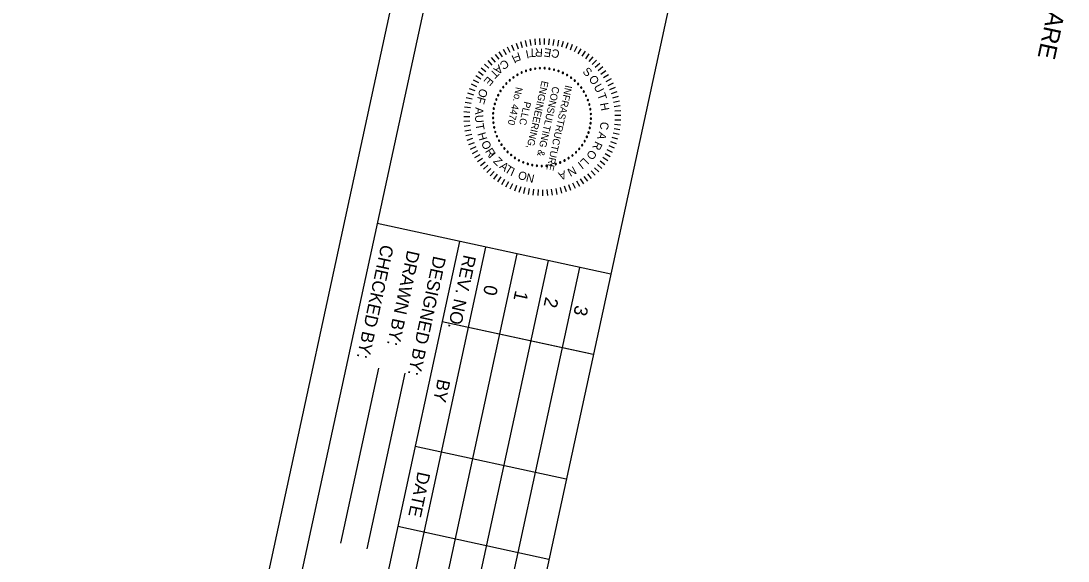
# Model space of a CAD drawing. Extents: x 1897817 to 2050613, y 442539 to 798440.
# Drawn here: x 1976813 to 1977576, y 783329 to 783723 of the extents above; entities that cross this region are included whole.
import ezdxf

# ---------------------------------------------------------------- set-up
doc = ezdxf.new("R2010")
doc.units = 0
for name, color, linetype in [('Default', 7, 'Continuous'), ('RD_SHT_Bndy', 7, 'Continuous'), ('RD_SHT_IplotShp', 7, 'Continuous')]:
    doc.layers.add(name, color=color, linetype=linetype)

msp = doc.modelspace()

# ---------------------------------------------------------------- linework, layer by layer
at = {"layer": 'Default'}
for p, q in [((1977174.02, 783706.47), (1977175.5, 783702.32)), ((1977177.35, 783707.54), (1977178.57, 783703.3)), ((1977180.73, 783708.4), (1977181.69, 783704.1)), ((1977184.16, 783709.06), (1977184.86, 783704.71)), ((1977187.62, 783709.5), (1977188.06, 783705.12)), ((1977191.11, 783709.74), (1977191.28, 783705.33)), ((1977194.6, 783709.76), (1977194.5, 783705.35)), ((1977198.09, 783709.57), (1977197.72, 783705.18)), ((1977201.56, 783709.16), (1977200.92, 783704.8)), ((1977205, 783708.55), (1977204.1, 783704.24)), ((1977208.39, 783707.72), (1977207.23, 783703.48)), ((1977211.73, 783706.7), (1977210.31, 783702.53)), ((1977158.7, 783698.21), (1977161.36, 783694.7)), ((1977161.55, 783700.23), (1977163.99, 783696.56)), ((1977164.52, 783702.07), (1977166.73, 783698.26)), ((1977167.6, 783703.73), (1977169.57, 783699.79)), ((1977170.77, 783705.2), (1977172.5, 783701.15)), ((1977215, 783705.47), (1977213.33, 783701.39)), ((1977218.19, 783704.04), (1977216.27, 783700.07)), ((1977221.28, 783702.42), (1977219.13, 783698.58)), ((1977224.27, 783700.62), (1977221.89, 783696.91)), ((1977227.15, 783698.63), (1977224.54, 783695.08)), ((1977150.96, 783691.17), (1977154.21, 783688.2)), ((1977153.4, 783693.68), (1977156.46, 783690.51)), ((1977155.98, 783696.03), (1977158.85, 783692.68)), ((1977229.9, 783696.48), (1977227.08, 783693.09)), ((1977232.51, 783694.16), (1977229.49, 783690.95)), ((1977234.98, 783691.68), (1977231.77, 783688.67)), ((1977146.57, 783685.74), (1977150.16, 783683.19)), ((1977148.68, 783688.52), (1977152.11, 783685.76)), ((1977237.29, 783689.07), (1977233.9, 783686.25)), ((1977239.43, 783686.31), (1977235.88, 783683.71)), ((1977241.41, 783683.43), (1977237.7, 783681.05)), ((1977141.3, 783676.7), (1977145.29, 783674.84)), ((1977142.87, 783679.82), (1977146.75, 783677.72)), ((1977144.63, 783682.84), (1977148.37, 783680.51)), ((1977243.2, 783680.43), (1977239.36, 783678.28)), ((1977244.81, 783677.33), (1977240.85, 783675.42)), ((1977138.74, 783670.2), (1977142.93, 783668.85)), ((1977139.92, 783673.49), (1977144.02, 783671.88)), ((1977246.23, 783674.14), (1977242.15, 783672.47)), ((1977247.45, 783670.87), (1977243.28, 783669.45)), ((1977136.99, 783663.44), (1977141.32, 783662.61)), ((1977137.76, 783666.85), (1977142.03, 783665.75)), ((1977248.47, 783667.53), (1977244.22, 783666.37)), ((1977249.28, 783664.13), (1977244.97, 783663.23)), ((1977249.89, 783660.69), (1977245.53, 783660.05)), ((1977135.94, 783653.03), (1977140.35, 783653)), ((1977136.08, 783656.52), (1977140.47, 783656.22)), ((1977136.43, 783660), (1977140.8, 783659.43)), ((1977250.28, 783657.22), (1977245.89, 783656.85)), ((1977250.46, 783653.73), (1977246.06, 783653.63)), ((1977136.01, 783649.54), (1977140.41, 783649.77)), ((1977136.3, 783646.06), (1977140.68, 783646.56)), ((1977250.18, 783646.75), (1977245.8, 783647.19)), ((1977250.43, 783650.24), (1977246.03, 783650.41)), ((1977136.8, 783642.6), (1977141.14, 783643.37)), ((1977137.51, 783639.18), (1977141.79, 783640.21)), ((1977248.18, 783636.48), (1977243.95, 783637.71)), ((1977249.06, 783639.86), (1977244.76, 783640.83)), ((1977249.73, 783643.29), (1977245.38, 783643.99)), ((1977138.43, 783635.81), (1977142.64, 783637.1)), ((1977139.55, 783632.5), (1977143.67, 783634.05)), ((1977140.87, 783629.27), (1977144.89, 783631.06)), ((1977245.83, 783629.91), (1977241.78, 783631.64)), ((1977247.11, 783633.16), (1977242.96, 783634.64)), ((1977142.38, 783626.12), (1977146.29, 783628.15)), ((1977144.08, 783623.07), (1977147.86, 783625.34)), ((1977145.97, 783620.13), (1977149.6, 783622.63)), ((1977240.83, 783620.71), (1977237.17, 783623.15)), ((1977242.68, 783623.67), (1977238.88, 783625.89)), ((1977244.35, 783626.74), (1977240.41, 783628.72)), ((1977148.03, 783617.31), (1977151.5, 783620.02)), ((1977150.26, 783614.62), (1977153.56, 783617.54)), ((1977152.65, 783612.07), (1977155.77, 783615.19)), ((1977234.25, 783612.57), (1977231.09, 783615.64)), ((1977236.61, 783615.15), (1977233.27, 783618.02)), ((1977238.81, 783617.87), (1977235.3, 783620.53)), ((1977155.19, 783609.68), (1977158.11, 783612.98)), ((1977157.87, 783607.44), (1977160.59, 783610.91)), ((1977160.69, 783605.37), (1977163.18, 783609)), ((1977163.62, 783603.47), (1977165.89, 783607.25)), ((1977223.39, 783603.84), (1977221.06, 783607.58)), ((1977226.3, 783605.77), (1977223.75, 783609.36)), ((1977229.09, 783607.87), (1977226.32, 783611.3)), ((1977231.74, 783610.14), (1977228.77, 783613.4)), ((1977166.66, 783601.76), (1977168.7, 783605.67)), ((1977169.81, 783600.24), (1977171.6, 783604.26)), ((1977173.04, 783598.91), (1977174.58, 783603.03)), ((1977176.34, 783597.78), (1977177.63, 783601.99)), ((1977179.71, 783596.85), (1977180.74, 783601.14)), ((1977183.13, 783596.13), (1977183.9, 783600.47)), ((1977186.58, 783595.62), (1977187.09, 783600)), ((1977190.06, 783595.33), (1977190.3, 783599.72)), ((1977193.56, 783595.24), (1977193.52, 783599.65)), ((1977197.05, 783595.37), (1977196.75, 783599.76)), ((1977200.52, 783595.71), (1977199.95, 783600.08)), ((1977203.97, 783596.26), (1977203.14, 783600.59)), ((1977207.38, 783597.02), (1977206.28, 783601.29)), ((1977210.74, 783597.99), (1977209.38, 783602.18)), ((1977214.03, 783599.16), (1977212.42, 783603.26)), ((1977217.24, 783600.53), (1977215.39, 783604.52)), ((1977220.37, 783602.09), (1977218.27, 783605.97)), ((1977243, 783538.14), (1977072.76, 783574.99)), ((1977132.8, 783561.98), (1977007.28, 782982.14)), ((1977151.76, 783557.88), (1977026.24, 782978.03)), ((1977174.51, 783552.96), (1977049.07, 782973.09)), ((1977197.34, 783548.01), (1977071.82, 782968.16)), ((1977220.24, 783543.06), (1977094.67, 782963.3)), ((1977120.09, 783503.65), (1977230.29, 783479.8)), ((1977120.09, 783503.65), (1977226.93, 783480.53)), ((1977073.83, 783469.6), (1977046.15, 783342.08)), ((1977092.95, 783465.86), (1977065.2, 783338.04)), ((1977100.52, 783412.86), (1977210.62, 783388.95)), ((1977087.87, 783354.44), (1977197.98, 783330.52))]:
    msp.add_line(p, q, dxfattribs=at)
for centre, start, end in [((1977175.02, 783683.42), 30.23602, 210.23602), ((1977175.02, 783683.42), 210.23602, 30.23602), ((1977178.08, 783685.01), 24.69756, 204.69756), ((1977178.08, 783685.01), 204.69756, 24.69756), ((1977181.28, 783686.29), 19.15909, 199.15909), ((1977181.28, 783686.29), 199.15909, 19.15909), ((1977184.59, 783687.25), 13.62063, 193.62063), ((1977184.59, 783687.25), 193.62063, 13.62063), ((1977187.98, 783687.9), 8.08217, 188.08217), ((1977187.98, 783687.9), 188.08217, 8.08217), ((1977191.41, 783688.21), 2.54371, 182.54371), ((1977191.41, 783688.21), 182.54371, 2.54371), ((1977194.86, 783688.19), 357.00525, 177.00525), ((1977194.86, 783688.19), 177.00525, 357.00525), ((1977198.29, 783687.83), 171.46679, 351.46679), ((1977198.29, 783687.83), 351.46679, 171.46679), ((1977201.67, 783687.15), 165.92833, 345.92833), ((1977201.67, 783687.15), 345.92833, 165.92833), ((1977204.96, 783686.15), 160.38986, 340.38986), ((1977204.96, 783686.15), 340.38986, 160.38986), ((1977208.15, 783684.83), 154.8514, 334.8514), ((1977208.15, 783684.83), 334.8514, 154.8514), ((1977211.19, 783683.21), 149.31294, 329.31294), ((1977211.19, 783683.21), 329.31294, 149.31294), ((1977166.94, 783677.01), 46.8514, 226.8514), ((1977166.94, 783677.01), 226.8514, 46.8514), ((1977169.42, 783679.41), 41.31294, 221.31294), ((1977169.42, 783679.41), 221.31294, 41.31294), ((1977172.12, 783681.55), 35.77448, 215.77448), ((1977172.12, 783681.55), 215.77448, 35.77448), ((1977214.07, 783681.3), 143.77448, 323.77448), ((1977214.07, 783681.3), 323.77448, 143.77448), ((1977216.74, 783679.13), 138.23602, 318.23602), ((1977216.74, 783679.13), 318.23602, 138.23602), ((1977219.19, 783676.7), 132.69756, 312.69756), ((1977219.19, 783676.7), 312.69756, 132.69756), ((1977161.03, 783668.56), 63.46679, 243.46679), ((1977161.03, 783668.56), 243.46679, 63.46679), ((1977162.72, 783671.57), 57.92833, 237.92833), ((1977162.72, 783671.57), 237.92833, 57.92833), ((1977164.7, 783674.39), 52.38986, 232.38986), ((1977164.7, 783674.39), 232.38986, 52.38986), ((1977221.4, 783674.06), 127.15909, 307.15909), ((1977221.4, 783674.06), 307.15909, 127.15909), ((1977223.34, 783671.21), 121.62063, 301.62063), ((1977223.34, 783671.21), 301.62063, 121.62063), ((1977225, 783668.18), 116.08217, 296.08217), ((1977225, 783668.18), 296.08217, 116.08217), ((1977158.55, 783662.14), 74.54371, 254.54371), ((1977158.55, 783662.14), 254.54371, 74.54371), ((1977159.64, 783665.41), 69.00525, 249.00525), ((1977159.64, 783665.41), 249.00525, 69.00525), ((1977226.36, 783665.01), 110.54371, 290.54371), ((1977226.36, 783665.01), 290.54371, 110.54371), ((1977227.4, 783661.73), 105.00525, 285.00525), ((1977227.4, 783661.73), 285.00525, 105.00525), ((1977157.25, 783651.91), 91.15909, 271.15909), ((1977157.35, 783655.35), 85.62063, 265.62063), ((1977157.25, 783651.91), 271.15909, 91.15909), ((1977157.79, 783658.77), 80.08217, 260.08217), ((1977157.35, 783655.35), 265.62063, 85.62063), ((1977157.79, 783658.77), 260.08217, 80.08217), ((1977228.13, 783658.36), 99.46679, 279.46679), ((1977228.52, 783654.93), 93.92833, 273.92833), ((1977228.13, 783658.36), 279.46679, 99.46679), ((1977228.52, 783654.93), 273.92833, 93.92833), ((1977157.48, 783648.47), 96.69756, 276.69756), ((1977157.48, 783648.47), 276.69756, 96.69756), ((1977158.04, 783645.07), 102.23602, 282.23602), ((1977158.04, 783645.07), 282.23602, 102.23602), ((1977227.72, 783644.65), 77.31294, 257.31294), ((1977227.72, 783644.65), 257.31294, 77.31294), ((1977228.32, 783648.05), 82.8514, 262.8514), ((1977228.59, 783651.49), 88.38986, 268.38986), ((1977228.32, 783648.05), 262.8514, 82.8514), ((1977228.59, 783651.49), 268.38986, 88.38986), ((1977158.92, 783641.73), 107.77448, 287.77448), ((1977158.92, 783641.73), 287.77448, 107.77448), ((1977160.13, 783638.5), 113.31294, 293.31294), ((1977160.13, 783638.5), 293.31294, 113.31294), ((1977225.55, 783638.12), 66.23602, 246.23602), ((1977225.55, 783638.12), 246.23602, 66.23602), ((1977226.79, 783641.33), 71.77448, 251.77448), ((1977226.79, 783641.33), 251.77448, 71.77448), ((1977161.64, 783635.4), 118.8514, 298.8514), ((1977161.64, 783635.4), 298.8514, 118.8514), ((1977163.44, 783632.46), 124.38986, 304.38986), ((1977163.44, 783632.46), 304.38986, 124.38986), ((1977165.52, 783629.71), 129.92833, 309.92833), ((1977165.52, 783629.71), 309.92833, 129.92833), ((1977220.06, 783629.39), 49.62063, 229.62063), ((1977220.06, 783629.39), 229.62063, 49.62063), ((1977222.17, 783632.12), 55.15909, 235.15909), ((1977222.17, 783632.12), 235.15909, 55.15909), ((1977224, 783635.03), 60.69756, 240.69756), ((1977224, 783635.03), 240.69756, 60.69756), ((1977167.85, 783627.17), 135.46679, 315.46679), ((1977167.85, 783627.17), 315.46679, 135.46679), ((1977170.42, 783624.87), 141.00525, 321.00525), ((1977170.42, 783624.87), 321.00525, 141.00525), ((1977173.19, 783622.83), 146.54371, 326.54371), ((1977173.19, 783622.83), 326.54371, 146.54371), ((1977212.3, 783622.6), 33.00525, 213.00525), ((1977212.3, 783622.6), 213.00525, 33.00525), ((1977215.1, 783624.61), 38.54371, 218.54371), ((1977215.1, 783624.61), 218.54371, 38.54371), ((1977217.69, 783626.88), 44.08217, 224.08217), ((1977217.69, 783626.88), 224.08217, 44.08217), ((1977176.15, 783621.06), 152.08217, 332.08217), ((1977176.15, 783621.06), 332.08217, 152.08217), ((1977179.27, 783619.59), 157.62063, 337.62063), ((1977179.27, 783619.59), 337.62063, 157.62063), ((1977182.52, 783618.43), 163.15909, 343.15909), ((1977182.52, 783618.43), 343.15909, 163.15909), ((1977185.86, 783617.58), 348.69756, 168.69756), ((1977185.86, 783617.58), 168.69756, 348.69756), ((1977189.27, 783617.07), 174.23602, 354.23602), ((1977189.27, 783617.07), 354.23602, 174.23602), ((1977192.71, 783616.88), 359.77448, 179.77448), ((1977192.71, 783616.88), 179.77448, 359.77448), ((1977196.16, 783617.03), 5.31294, 185.31294), ((1977196.16, 783617.03), 185.31294, 5.31294), ((1977199.57, 783617.5), 10.8514, 190.8514), ((1977199.57, 783617.5), 190.8514, 10.8514), ((1977202.92, 783618.31), 16.38986, 196.38986), ((1977202.92, 783618.31), 196.38986, 16.38986), ((1977206.18, 783619.43), 21.92833, 201.92833), ((1977206.18, 783619.43), 201.92833, 21.92833), ((1977209.32, 783620.87), 27.46679, 207.46679), ((1977209.32, 783620.87), 207.46679, 27.46679)]:
    msp.add_arc(centre, 0.485, start, end, dxfattribs=at)
at = {"layer": 'RD_SHT_Bndy'}
for p, q in [((1977385.46, 785019.62), (1976842.49, 782511.26)), ((1977388.81, 784211.78), (1977012.76, 782474.48)), ((1977243, 783538.13), (1977072.76, 783575.06))]:
    msp.add_line(p, q, dxfattribs=at)
at = {"layer": 'RD_SHT_IplotShp'}
msp.add_lwpolyline([(1977366.14, 785041.72), (1976813.35, 782487.96), (1978459.81, 782131.57), (1979012.6, 784685.33)], close=True, dxfattribs=at)

# ---------------------------------------------------------------- texts
at = {"layer": 'Default'}
for s, height, rotation, p in [('ITS DEVICES/SYMBOLOGY (CAMERA, SERVICE BOX, DMS, CABINET, ETC.) ARE SCALED UP FOR VISIBILITY ON PLANS, THEY ARE', 12.70566, 257.78611, (1977779.42, 784738.12)), ('F', 6.03, 197.55738, (1977176.3, 783699.98)), ('I', 6.03, 191.55738, (1977182.72, 783701.5)), ('T', 6.03, 182.81115, (1977188.1, 783702.44)), ('R', 6.03, 176.81115, (1977193.68, 783702.46)), ('E', 6.03, 170.81115, (1977200.11, 783701.98)), ('C', 6.03, 164.81115, (1977206.36, 783700.93)), ('A', 6.03, 218.31294, (1977161.45, 783691.11)), ('C', 6.03, 212.31294, (1977166.43, 783694.93)), ('I', 6.03, 206.31294, (1977172.04, 783697.92)), ('T', 6.03, 224.31294, (1977158.05, 783687.99)), ('S', 6.03, 316.69438, (1977222.06, 783685.15)), ('E', 6.03, 230.31294, (1977153.53, 783682.7)), ('ENGINEERING,', 5.1733, 257.31294, (1977192.72, 783679.31)), ('INFRASTRUCTURE', 5.1733, 257.31294, (1977210.01, 783676.11)), ('O', 6.03, 307.66435, (1977226.53, 783680.26)), ('U', 6.03, 298.63433, (1977230.35, 783674.69)), ('O', 6.03, 248.31294, (1977148.17, 783673.94)), ('No. 4470', 5.173, 257.31294, (1977173.99, 783674.72)), ('CONSULTING &', 5.1733, 257.31294, (1977200.71, 783675.21)), ('T', 6.03, 289.6043, (1977233.07, 783668.91)), ('F', 6.03, 254.31294, (1977146.22, 783667.89)), ('PLLC', 5.173, 257.31294, (1977180, 783664.25)), ('H', 6.03, 280.57428, (1977235.05, 783662.47)), ('U', 6.03, 274.31294, (1977144.03, 783653.94)), ('A', 6.03, 268.31294, (1977144.35, 783659.81)), ('T', 6.03, 280.31294, (1977144.34, 783647.38)), ('C', 6.03, 262.51423, (1977235.72, 783649.39)), ('H', 6.03, 286.31294, (1977145.8, 783640.46)), ('A', 6.03, 253.4842, (1977234.52, 783642.25)), ('O', 6.03, 296.31294, (1977148.3, 783633.68)), ('R', 6.03, 302.31294, (1977151.23, 783627.63)), ('R', 6.03, 244.45418, (1977231.85, 783635.45)), ('I', 6.03, 310.11999, (1977153.71, 783623.6)), ('Z', 6.03, 315.18149, (1977157.01, 783619.98)), ('L', 6.03, 224.89413, (1977223.54, 783623.33)), ('O', 6.03, 235.42415, (1977228.4, 783629.27)), ('A', 6.03, 321.18149, (1977161.53, 783615.89)), ('T', 6.03, 327.18149, (1977165.16, 783612.93)), ('I', 6.03, 335.69537, (1977169.34, 783610.2)), ('N', 6.03, 208.33408, (1977215.89, 783616.96)), ('I', 6.03, 217.3641, (1977220.22, 783620.33)), ('O', 6.03, 340.9946, (1977174.82, 783607.92)), ('N', 6.03, 346.9946, (1977180.84, 783605.83)), ('A', 6.03, 199.30405, (1977209.37, 783613.77)), ('CHECKED BY:', 9.326, 257.78595, (1977075.84, 783560.06)), ('DRAWN BY:', 9.326, 257.78595, (1977094.87, 783555.94)), ('DESIGNED BY:', 9.3265, 257.78595, (1977113.91, 783551.82)), ('REV. NO.', 9.335, 257.78595, (1977135.88, 783552.65)), ('0', 9.75, 257.78611, (1977151.44, 783530.85)), ('1', 9.75, 257.78611, (1977173.56, 783526.67)), ('2', 9.75, 257.78611, (1977195.55, 783521.91)), ('3', 9.75, 257.78611, (1977217.28, 783515.98)), ('BY', 9.335, 257.78595, (1977117.12, 783462.18)), ('DATE', 9.335, 257.78595, (1977102.51, 783394.66))]:
    msp.add_text(s, height=height, rotation=rotation, dxfattribs=at).set_placement(p)

doc.saveas('drawing.dxf')
